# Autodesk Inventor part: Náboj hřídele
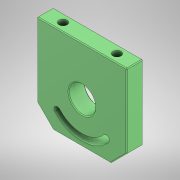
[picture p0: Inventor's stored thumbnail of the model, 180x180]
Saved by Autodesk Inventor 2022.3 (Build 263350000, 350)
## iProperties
Created: 2025-11
Part Number: Náboj hřídele
Material: Všeobecné
Document SubType Name: Modeling
Designer: Hra42
Density: 1 g/cm^3
Appearance: Výchozí
Author: Hra42
Sending System: SolidWorks 2012
Last Author: Hra42
Last Saved: 2025-11-10
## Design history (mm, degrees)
node "Náboj hřídele.SLDPRT"
node "Těleso1"
feature "Odebrat vysunutím1"
